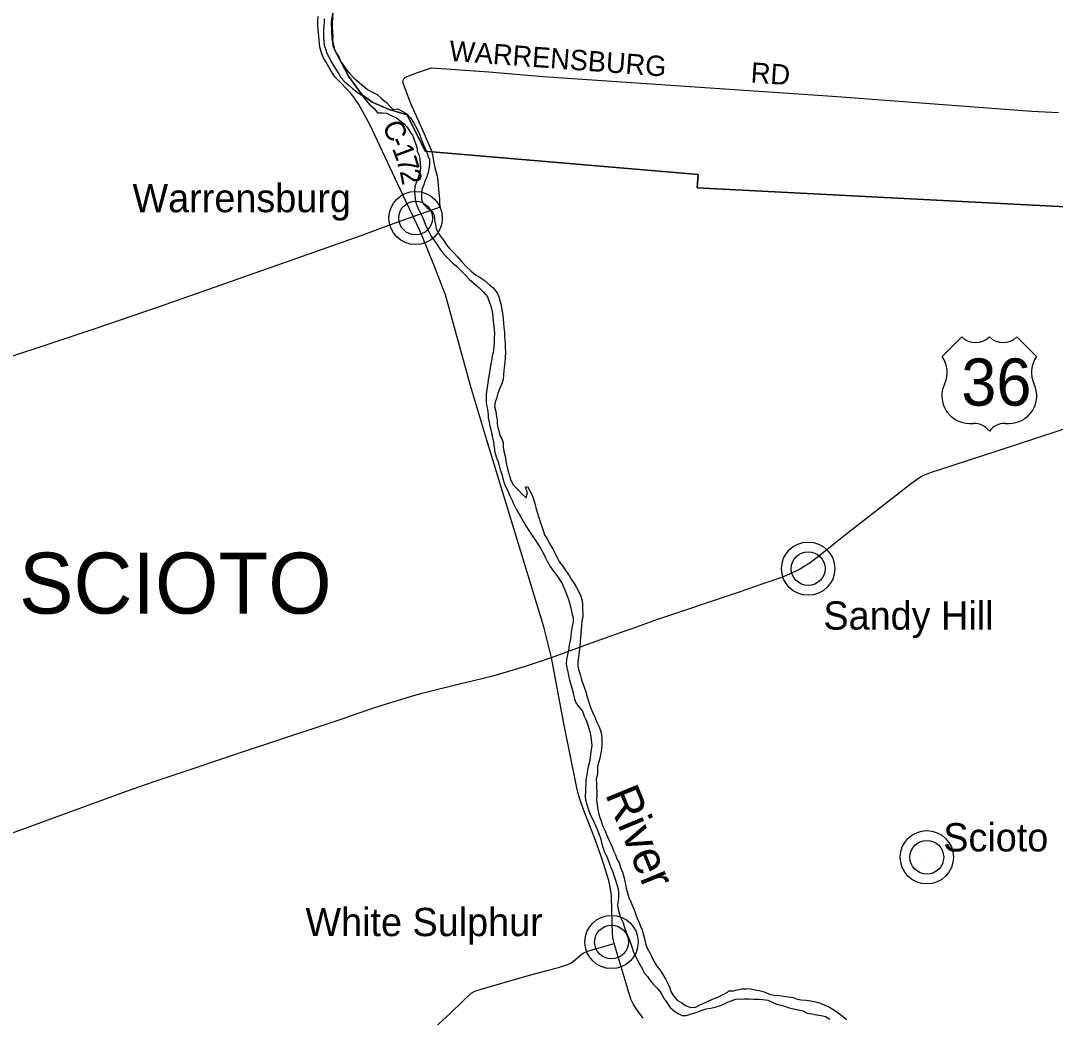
# Model space of a CAD drawing. Extents: x 1674899 to 2057726, y 653888 to 988278.
# Drawn here: x 1776320 to 1791586, y 828834 to 843541 of the extents above; entities that cross this region are included whole.
import ezdxf

# ---------------------------------------------------------------- set-up
doc = ezdxf.new("R2010")
doc.units = 0
for name, color, linetype in [('GM_X_County_Road', 7, 'Continuous'), ('GM_X_County_Road_Text', 7, 'Continuous'), ('GM_X_Major_River', 7, 'Continuous'), ('GM_X_Major_River_Text', 7, 'Continuous'), ('GM_X_State_Route', 7, 'Continuous'), ('GM_X_Township', 7, 'Continuous'), ('GM_X_Township_Text', 7, 'Continuous'), ('GM_X_Unincorporated', 7, 'Continuous'), ('GM_X_Unincorporated_Location', 7, 'Continuous'), ('GM_X_Unincorporated_Text', 7, 'Continuous'), ('GM_X_US_Route', 7, 'Continuous'), ('GM_X_US_Shield', 7, 'Continuous'), ('SH_Data', 7, 'Continuous')]:
    doc.layers.add(name, color=color, linetype=linetype)

msp = doc.modelspace()

# ---------------------------------------------------------------- linework, layer by layer
at = {"layer": 'GM_X_County_Road'}
for points in [[(1782409, 841508), (1782391, 841606), (1782242, 841946), (1782072, 842331), (1781962, 842618), (1781962, 842650), (1781965, 842662), (1781975, 842683), (1782000, 842708), (1782174, 842776), (1782382, 842844), (1783229, 842784), (1784027, 842716), (1788298, 842429), (1791241, 842207), (1791633, 842186)], [(1782516, 840796), (1782504, 840822), (1782504, 840849), (1782503, 840907), (1782496, 840999), (1782473, 841224), (1782437, 841372), (1782421, 841443), (1782409, 841508)], [(1782111, 840650), (1782111, 840650), (1782516, 840796)], [(1779079, 839573), (1781342, 840372), (1781765, 840527), (1782111, 840650)], [(1776147, 838574), (1776742, 838771), (1777434, 839004), (1778366, 839322), (1779079, 839573)], [(1782216, 828486), (1782656, 828889), (1782857, 829086), (1782966, 829190), (1783022, 829221), (1783116, 829251), (1783761, 829437), (1784081, 829523), (1784256, 829568), (1784391, 829611), (1784435, 829632), (1784475, 829661), (1784511, 829694), (1784590, 829760), (1784631, 829786), (1784675, 829805), (1784739, 829825), (1785075, 829924)]]:
    msp.add_lwpolyline(points, dxfattribs=at)
at = {"layer": 'GM_X_Major_River'}
for points in [[(1780797, 843570), (1780797, 843520), (1780792, 843470), (1780788, 843418), (1780787, 843291), (1780791, 843241), (1780800, 843177), (1780818, 843125), (1780839, 843062), (1780869, 842996), (1780896, 842944), (1780936, 842881), (1780975, 842817), (1781015, 842755), (1781044, 842702), (1781096, 842646), (1781166, 842585), (1781217, 842541), (1781283, 842484), (1781356, 842439), (1781418, 842365), (1781471, 842298), (1781535, 842246), (1781586, 842183), (1781656, 842180), (1781724, 842174), (1781798, 842139), (1781864, 842105), (1781915, 842070), (1781973, 842022), (1782021, 841969), (1782062, 841907), (1782104, 841840), (1782133, 841770), (1782157, 841706), (1782172, 841651)], [(1780925, 843595), (1780917, 843527), (1780914, 843447), (1780922, 843374), (1780925, 843306), (1780923, 843240), (1780924, 843166), (1780948, 843116), (1780977, 843065), (1781017, 842997), (1781040, 842943), (1781084, 842878), (1781131, 842812), (1781187, 842745), (1781244, 842687), (1781320, 842626), (1781373, 842579), (1781435, 842527), (1781509, 842486), (1781578, 842450), (1781644, 842393), (1781717, 842336), (1781763, 842284), (1781817, 842229), (1781881, 842241), (1781948, 842208), (1782016, 842168), (1782072, 842109), (1782115, 842039), (1782147, 841984), (1782182, 841920), (1782204, 841866), (1782227, 841797), (1782255, 841733), (1782280, 841675), (1782310, 841610), (1782329, 841558)], [(1782172, 841651), (1782172, 841617), (1782195, 841565), (1782209, 841503), (1782216, 841439), (1782220, 841369), (1782207, 841298), (1782189, 841243), (1782160, 841163), (1782136, 841089), (1782131, 841025), (1782135, 840952), (1782144, 840880), (1782166, 840812), (1782195, 840744), (1782233, 840675), (1782262, 840609), (1782290, 840540), (1782319, 840474), (1782351, 840410), (1782378, 840359), (1782424, 840293), (1782459, 840243), (1782505, 840174), (1782556, 840104), (1782618, 840041), (1782689, 839970), (1782751, 839918), (1782814, 839857), (1782878, 839790), (1782939, 839728), (1783011, 839661), (1783080, 839602), (1783146, 839540), (1783207, 839465), (1783227, 839409), (1783246, 839359), (1783268, 839294), (1783281, 839220), (1783285, 839168), (1783290, 839112), (1783305, 838988), (1783309, 838917), (1783308, 838867), (1783308, 838799), (1783303, 838725), (1783289, 838645), (1783278, 838595), (1783270, 838545), (1783257, 838475), (1783249, 838413), (1783236, 838351), (1783226, 838301), (1783218, 838235), (1783209, 838163), (1783198, 838093), (1783190, 838029), (1783188, 837977), (1783189, 837919), (1783195, 837862), (1783206, 837804), (1783216, 837730), (1783219, 837678), (1783231, 837616), (1783240, 837564), (1783260, 837491), (1783273, 837439), (1783283, 837383), (1783294, 837323), (1783304, 837250), (1783315, 837174), (1783335, 837104), (1783364, 837032), (1783382, 836975), (1783397, 836911), (1783417, 836849), (1783440, 836767), (1783465, 836688), (1783493, 836634), (1783516, 836578), (1783546, 836511), (1783572, 836459), (1783595, 836401), (1783631, 836334), (1783660, 836282), (1783690, 836232), (1783737, 836145), (1783775, 836089), (1783816, 836018), (1783867, 835946), (1783913, 835879), (1783946, 835827), (1783992, 835759), (1784029, 835690), (1784063, 835616), (1784088, 835565), (1784132, 835487), (1784165, 835437), (1784217, 835372), (1784258, 835310), (1784308, 835235)], [(1782329, 841558), (1782325, 841548), (1782351, 841494), (1782354, 841424), (1782342, 841352), (1782329, 841286), (1782307, 841224), (1782284, 841172), (1782266, 841120), (1782241, 841050), (1782233, 840978), (1782236, 840906), (1782260, 840837), (1782319, 840781), (1782385, 840734), (1782419, 840670), (1782428, 840599), (1782439, 840531), (1782451, 840475), (1782473, 840413), (1782526, 840346), (1782562, 840296), (1782603, 840233), (1782649, 840179), (1782710, 840114), (1782764, 840056), (1782829, 839981), (1782895, 839913), (1782962, 839848), (1783034, 839787), (1783085, 839759), (1783157, 839712), (1783240, 839639), (1783292, 839599), (1783349, 839526), (1783375, 839468), (1783389, 839414), (1783404, 839362), (1783414, 839307), (1783423, 839255), (1783433, 839191), (1783438, 839135), (1783442, 839081), (1783449, 839013), (1783457, 838936), (1783458, 838880), (1783462, 838830), (1783466, 838770), (1783469, 838712), (1783471, 838660), (1783470, 838558), (1783464, 838507), (1783459, 838457), (1783449, 838381), (1783444, 838315), (1783440, 838247), (1783415, 838171), (1783391, 838117), (1783362, 838045), (1783339, 837965), (1783321, 837914), (1783312, 837849), (1783330, 837775), (1783339, 837701), (1783349, 837649), (1783351, 837599), (1783362, 837539), (1783374, 837488), (1783391, 837420), (1783421, 837370), (1783440, 837314), (1783438, 837241), (1783453, 837165), (1783475, 837093), (1783478, 837041), (1783490, 836991), (1783505, 836926), (1783519, 836876), (1783532, 836824), (1783552, 836762), (1783591, 836687), (1783659, 836619), (1783714, 836558), (1783776, 836501), (1783796, 836573), (1783766, 836659), (1783796, 836665), (1783874, 836529), (1783891, 836463), (1783909, 836398), (1783928, 836340), (1783942, 836290), (1783960, 836226), (1783983, 836145), (1784005, 836091), (1784024, 836031), (1784051, 835956), (1784099, 835878), (1784122, 835828), (1784182, 835727), (1784207, 835673)], [(1784207, 835673), (1784239, 835612), (1784266, 835562), (1784316, 835494), (1784363, 835421), (1784411, 835355), (1784444, 835302), (1784486, 835234), (1784521, 835177), (1784557, 835111), (1784586, 835049), (1784604, 834978), (1784609, 834926), (1784609, 834848), (1784614, 834796), (1784612, 834738), (1784601, 834686), (1784595, 834604), (1784590, 834552), (1784586, 834500), (1784581, 834444), (1784577, 834382), (1784570, 834306), (1784566, 834255), (1784553, 834187), (1784547, 834117), (1784540, 834067), (1784542, 834017), (1784557, 833953), (1784573, 833895), (1784596, 833814), (1784614, 833760), (1784633, 833708), (1784659, 833638), (1784680, 833561), (1784698, 833499), (1784715, 833449), (1784733, 833395), (1784756, 833336), (1784790, 833262), (1784821, 833190), (1784853, 833131), (1784874, 833065), (1784890, 833013), (1784897, 832933), (1784897, 832863), (1784892, 832796), (1784878, 832732), (1784865, 832660), (1784851, 832606), (1784832, 832533), (1784830, 832480), (1784831, 832416), (1784813, 832352), (1784816, 832282), (1784818, 832218), (1784821, 832162), (1784823, 832102), (1784818, 832034), (1784824, 831978), (1784829, 831924), (1784845, 831853), (1784864, 831783), (1784886, 831727), (1784911, 831654), (1784941, 831594), (1784966, 831532), (1784994, 831461), (1785023, 831403), (1785047, 831349), (1785068, 831291), (1785098, 831232), (1785117, 831174), (1785149, 831112), (1785172, 831047), (1785200, 830977), (1785217, 830909), (1785233, 830843), (1785244, 830792), (1785256, 830738), (1785273, 830672), (1785295, 830600), (1785322, 830539), (1785344, 830489), (1785373, 830419), (1785393, 830365), (1785412, 830308), (1785438, 830252), (1785467, 830180), (1785491, 830123), (1785512, 830049), (1785522, 829997), (1785537, 829919), (1785565, 829854), (1785602, 829786), (1785630, 829736), (1785669, 829655), (1785706, 829587), (1785750, 829534), (1785795, 829466), (1785841, 829393)], [(1784308, 835235), (1784329, 835185), (1784361, 835117), (1784378, 835066), (1784400, 835014), (1784419, 834948), (1784435, 834876), (1784454, 834805), (1784470, 834729), (1784471, 834673), (1784455, 834599), (1784442, 834523), (1784435, 834447), (1784425, 834377), (1784414, 834327), (1784404, 834253), (1784387, 834185), (1784371, 834115), (1784368, 834057), (1784376, 833991), (1784391, 833930), (1784405, 833878), (1784420, 833808), (1784444, 833728), (1784465, 833641), (1784479, 833591), (1784490, 833535), (1784512, 833477), (1784559, 833412), (1784611, 833350), (1784636, 833277), (1784660, 833227), (1784681, 833165), (1784703, 833098), (1784724, 833032), (1784734, 832970), (1784741, 832894), (1784745, 832844), (1784728, 832724), (1784725, 832658), (1784715, 832606), (1784692, 832530), (1784684, 832480), (1784673, 832412), (1784661, 832342), (1784658, 832283), (1784656, 832219), (1784655, 832169), (1784649, 832097), (1784654, 832041), (1784672, 831975), (1784697, 831895), (1784717, 831840), (1784742, 831786), (1784772, 831734), (1784801, 831665), (1784833, 831597), (1784856, 831533), (1784878, 831464), (1784891, 831410), (1784916, 831330), (1784936, 831270), (1784966, 831215), (1784989, 831151), (1785009, 831101), (1785030, 831043), (1785052, 830992), (1785073, 830930), (1785093, 830874), (1785110, 830807), (1785134, 830729), (1785139, 830663), (1785141, 830593), (1785130, 830533), (1785126, 830481), (1785135, 830429), (1785155, 830358), (1785172, 830306), (1785208, 830228), (1785227, 830160), (1785253, 830091), (1785276, 830041), (1785300, 829987), (1785321, 829920), (1785347, 829846), (1785360, 829796), (1785394, 829736), (1785417, 829685), (1785453, 829623), (1785488, 829556), (1785518, 829490), (1785569, 829436), (1785609, 829375), (1785652, 829321), (1785710, 829266), (1785755, 829210), (1785787, 829159), (1785816, 829105), (1785856, 829055), (1785905, 828980), (1785967, 828924)], [(1785841, 829393), (1785872, 829325), (1785896, 829271), (1785915, 829215), (1785951, 829152), (1786006, 829086), (1786076, 829049), (1786140, 829004), (1786207, 828978), (1786277, 828983), (1786340, 829019), (1786390, 829039), (1786456, 829066), (1786528, 829100), (1786606, 829131), (1786675, 829166), (1786747, 829206)], [(1786747, 829206), (1786769, 829224), (1786839, 829227), (1786893, 829239), (1786959, 829254), (1787029, 829256), (1787081, 829261), (1787155, 829241), (1787235, 829224), (1787307, 829206), (1787379, 829173), (1787446, 829160), (1787512, 829154), (1787576, 829145), (1787648, 829137), (1787718, 829126), (1787778, 829104), (1787838, 829091), (1787910, 829085), (1787980, 829076), (1788055, 829063), (1788119, 829045), (1788187, 829012), (1788253, 828984), (1788316, 828945), (1788380, 828901), (1788442, 828854), (1788503, 828800)], [(1785967, 828924), (1786019, 828891), (1786080, 828859), (1786142, 828862), (1786215, 828884), (1786287, 828903), (1786359, 828937), (1786433, 828958), (1786499, 828970), (1786569, 828983), (1786633, 829001), (1786696, 829028), (1786750, 829056), (1786804, 829075), (1786874, 829103)], [(1786874, 829103), (1786894, 829105), (1786946, 829100), (1786998, 829108), (1787064, 829109), (1787136, 829103), (1787210, 829102), (1787272, 829096), (1787342, 829085), (1787410, 829057), (1787473, 829026), (1787543, 829011), (1787607, 828993), (1787659, 828976), (1787729, 828958), (1787795, 828943), (1787860, 828931), (1787926, 828894), (1787996, 828886), (1788064, 828871), (1788130, 828861), (1788196, 828848), (1788257, 828805)]]:
    msp.add_lwpolyline(points, dxfattribs=at)
at = {"layer": 'GM_X_State_Route'}
for points in [[(1782426, 839915), (1782250, 840350), (1782172, 840527), (1782111, 840650), (1781955, 840981), (1781476, 841997), (1781310, 842306), (1781236, 842414), (1781182, 842481), (1780990, 842678), (1780970, 842699), (1780952, 842720), (1780919, 842766), (1780783, 843002), (1780756, 843068), (1780736, 843152), (1780719, 843314), (1780704, 843467), (1780704, 843535), (1780710, 843602)], [(1785504, 828821), (1785420, 828937), (1785361, 829025), (1785323, 829103), (1785237, 829384), (1785075, 829924), (1785057, 830010), (1785050, 830079), (1785047, 830234), (1785036, 830617), (1785033, 830668), (1785019, 830761), (1784998, 830853), (1784946, 831027), (1784900, 831165), (1784850, 831306), (1784785, 831484), (1784615, 831925), (1784558, 832087), (1784544, 832136), (1784524, 832218), (1784335, 833168), (1784151, 834144), (1784039, 834594), (1783197, 837352), (1782964, 838137), (1782587, 839495), (1782452, 839852), (1782426, 839915)]]:
    msp.add_lwpolyline(points, dxfattribs=at)
at = {"layer": 'GM_X_Township'}
for points in [[(1794218, 845643), (1793954, 842199), (1793839, 840685), (1786300, 841075), (1786314, 841270), (1782391, 841606), (1782290, 841614), (1782021, 842150), (1781758, 842232), (1781508, 842340), (1781351, 842454), (1781155, 842721), (1780952, 843117), (1780916, 843270), (1780907, 843520), (1780980, 844003)], [(1780980, 844003), (1780907, 843520), (1780916, 843270), (1780952, 843117), (1781155, 842721), (1781351, 842454), (1781508, 842340), (1781758, 842232), (1782021, 842150), (1782290, 841614), (1782391, 841606), (1786314, 841270), (1786300, 841075), (1793839, 840685)]]:
    msp.add_lwpolyline(points, dxfattribs=at)
at = {"layer": 'GM_X_Unincorporated'}
for centre, radius in [((1782147, 840629), 393), ((1782147, 840629), 249), ((1787939, 835455), 393), ((1787939, 835455), 249), ((1789690, 831196), 393), ((1789690, 831196), 249), ((1785038, 829945), 393), ((1785038, 829945), 249)]:
    msp.add_circle(centre, radius, dxfattribs=at)
at = {"layer": 'GM_X_Unincorporated_Location'}
for p, q in [((1782147, 840629), (1782147, 840629)), ((1787939, 835455), (1787939, 835455)), ((1789690, 831196), (1789690, 831196)), ((1785038, 829945), (1785038, 829945))]:
    msp.add_line(p, q, dxfattribs=at)
at = {"layer": 'GM_X_US_Route'}
for points in [[(1785291, 834555), (1785341, 834572), (1785723, 834708), (1786913, 835110), (1787149, 835192), (1787535, 835324), (1787660, 835373), (1787802, 835441), (1787953, 835536), (1788092, 835640), (1788316, 835821), (1788577, 836027), (1789200, 836511), (1789464, 836715), (1789512, 836752), (1789559, 836786), (1789581, 836800), (1789608, 836815), (1789657, 836839), (1789708, 836860), (1789760, 836879), (1789880, 836917), (1790713, 837188), (1791944, 837592)], [(1784151, 834144), (1784673, 834334), (1785291, 834555)], [(1781140, 833266), (1781530, 833400), (1781652, 833441), (1782073, 833569), (1782240, 833615), (1782816, 833759), (1782964, 833793), (1783306, 833880), (1783524, 833942), (1783770, 834017), (1784151, 834144)], [(1773271, 830397), (1773379, 830444), (1774387, 830877), (1775615, 831340), (1776007, 831488), (1777883, 832171), (1778258, 832305), (1778909, 832522), (1779520, 832725), (1780843, 833166), (1781136, 833265), (1781140, 833266)]]:
    msp.add_lwpolyline(points, dxfattribs=at)
at = {"layer": 'GM_X_US_Shield'}
for p, q in [((1790207, 838875), (1789917, 838585)), ((1791309, 838585), (1791019, 838875)), ((1790323, 837599), (1790381, 837599)), ((1790845, 837599), (1790903, 837599))]:
    msp.add_line(p, q, dxfattribs=at)
for centre, radius, start, end in [((1790410, 839082), 290, 225.573, 314.427), ((1790816, 839082), 290, 225.573, 314.427), ((1789584, 838352), 406, 334.5471, 35.0009), ((1791641, 838352), 406, 144.9991, 205.4529), ((1790318, 838005), 406, 154.8319, 270.6383), ((1790907, 838005), 406, 269.3617, 25.1681), ((1790381, 837309), 290, 36.8699, 90), ((1790845, 837309), 290, 90, 143.1301)]:
    msp.add_arc(centre, radius, start, end, dxfattribs=at)
at = {"layer": 'SH_Data'}
for points in [[(1785291, 834555), (1785341, 834572), (1785723, 834708), (1786913, 835110), (1787149, 835192), (1787535, 835324), (1787660, 835373), (1787802, 835441), (1787953, 835536), (1788092, 835640), (1788316, 835821), (1788577, 836027), (1789200, 836511), (1789464, 836715), (1789512, 836752), (1789559, 836786), (1789581, 836800), (1789608, 836815), (1789657, 836839), (1789708, 836860), (1789760, 836879), (1789880, 836917), (1790713, 837188), (1791944, 837592)], [(1784151, 834144), (1784673, 834334), (1785291, 834555)], [(1781140, 833266), (1781530, 833400), (1781652, 833441), (1782073, 833569), (1782240, 833615), (1782816, 833759), (1782964, 833793), (1783306, 833880), (1783524, 833942), (1783770, 834017), (1784151, 834144)], [(1773271, 830397), (1773379, 830444), (1774387, 830877), (1775615, 831340), (1776007, 831488), (1777883, 832171), (1778258, 832305), (1778909, 832522), (1779520, 832725), (1780843, 833166), (1781136, 833265), (1781140, 833266)]]:
    msp.add_lwpolyline(points, dxfattribs=at)

# ---------------------------------------------------------------- texts
at = {"layer": 'GM_X_County_Road_Text'}
for s, rotation, p in [('WARRENSBURG', 355.7995, (1782635, 842950)), ('RD', 356.0551, (1787085, 842629)), ('C', 293.7065, (1781650, 841993)), ('1', 290.5311, (1781796, 841658)), ('-', 292.8619, (1781749, 841768)), ('7', 286.929, (1781859, 841489)), ('2', 281.6324, (1781911, 841320))]:
    msp.add_text(s, height=300, rotation=rotation, dxfattribs=at).set_placement(p)
at = {"layer": 'GM_X_Major_River_Text'}
msp.add_text('River', height=500, rotation=292.4162, dxfattribs=at).set_placement((1784939, 832128))
at = {"layer": 'GM_X_Township_Text'}
msp.add_text('SCIOTO', height=900, rotation=0, dxfattribs=at).set_placement((1776295, 834791))
at = {"layer": 'GM_X_Unincorporated_Text'}
for s, p in [('Warrensburg', (1777969, 840715)), ('Sandy Hill', (1788164, 834555)), ('Scioto', (1789933, 831282)), ('White Sulphur', (1780521, 830032))]:
    msp.add_text(s, height=417, rotation=0, dxfattribs=at).set_placement(p)
at = {"layer": 'GM_X_US_Shield'}
msp.add_text('36', height=696.1, dxfattribs=at).set_placement((1790199, 837860))

doc.saveas('drawing.dxf')
